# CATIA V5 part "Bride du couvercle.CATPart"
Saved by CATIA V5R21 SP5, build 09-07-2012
Part number: Bride du couvercle
Bounding box of the stored display mesh (mm): x -2589.279 to 2589.279, y -2586.606 to 2586.606, z 0 to 1029.022
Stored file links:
  \\etu.ad.univ-lorraine.fr\bordron1\Documents\Parts EPR\Bride du couvercle.CATPart
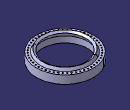
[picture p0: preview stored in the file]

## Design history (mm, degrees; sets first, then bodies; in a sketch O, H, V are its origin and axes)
AxisSystem1: origin (0, 0, 0), X (1, 0, 0), Y (0, 1, 0), Z (0, 0, 1)
Body1 (main body)
  Sketch1 on YZ plane of AxisSystem1, origin (0, 0, 0), H (0, 1, 0), V (0, 0, 1)
    line L1 (-2590, 787) -> (-2590, 37)
    point P2 (-2590, 37)
    line L2 (-2065, 558.7392) -> (-2065, 0)
    reference intersected line E1 through (0, 0) direction (0, 1) from ZX plane of AxisSystem1
    line L3 (-2065, 0) -> (-2215, 0)
    line L4 (-2215, 0) -> (-2215, 37)
    line L5 (-2215, 37) -> (-2590, 37)
    point P7 (-2590, 37)
    reference intersected line E2 through (0, 0) direction (-1, 0) from XY plane of AxisSystem1
    line L6 (-2590, 787) -> (-2215, 787)
    arc A1 centre (0, -319.504) radius 2244 from (-1881.9768, 902.666) to (-2065, 558.7392) ccw
    point P9 (0, -319.504)
    arc A2 centre (0, -319.504) radius 2476 from (-2076.5483, 1029.0223) to (-2215, 787) ccw
    point P11 (0, -319.504)
    line L7 (-1881.9768, 902.666) -> (-2076.5483, 1029.0223)
    axis line L8 (0, -319.504) -> (-1881.9768, 902.666)
    reference projected line E3 through (0, 0) direction (0, 1) from edge [ZX plane of AxisSystem1 | YZ plane of AxisSystem1]
    distance L2 E1 = 2065
    distance L2 L1 = 525
    length L4 = 37
    length L3 = 150
    length L1 = 750
    radius A1 = 2244
    radius A2 = 2476
    length L6 = 375
    angle E3 L7 = 57
    vertical: L1 V, L2 V, L4 V
    horizontal: L3 H, L5 H, L6 H
    coincidence: P2 P7, L3 E2, P9 V, P11 P9
    parallelism: L8 L7
  Shaft1: profile Sketch1, axis edge [ZX plane of AxisSystem1 | YZ plane of AxisSystem1], angle 360
  Sketch2 on XY plane of AxisSystem1, origin (0, 0, 0), H (1, 0, 0), V (0, 1, 0)
    circle A1 centre (0, 2402) radius 60
    point P1 (0, 2402)
    radius A1 = 60
    distance P1 O = 2402
    coincidence: P1 V
  Pocket1: profile Sketch2, direction (0, 0, -1), through (limit type 6), opposite side length 20
  CircPattern1: of Pocket1, instances 52, angular step 6.923, axis from edge [ZX plane of AxisSystem1 | YZ plane of AxisSystem1]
